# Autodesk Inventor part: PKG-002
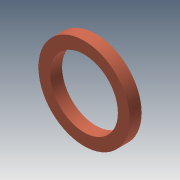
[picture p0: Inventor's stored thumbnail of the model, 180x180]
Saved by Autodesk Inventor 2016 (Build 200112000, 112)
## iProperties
Created: 2013-11
Part Number: PKG-002
Material: Nylon 6/6
Document SubType Name: Modeling
Designer: normanpa
Density: 1.13 g/cm^3
Appearance: 255,135,102
Description: INNER GEAR PACKING
Mass: 8.17565 g
Surface Area: 41.3434 cm^2
Volume: 7.23509 cm^3
Author: Autodesk
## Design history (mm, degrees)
sketch "Sketch1"
  geometry: C1 r 27 at (0, 0); C2 r 20 at (0, 0); 1 further point
  constraints: 2 centre point, 2 coincident
  dimensions: "d0" = 54 diameter of C1; "d1" = 40 diameter of C2
extrude "Extrusion1" new body sketch "Sketch1" distance "d2" = 7; taper "d3" = 0 deg
body "Solid1"
